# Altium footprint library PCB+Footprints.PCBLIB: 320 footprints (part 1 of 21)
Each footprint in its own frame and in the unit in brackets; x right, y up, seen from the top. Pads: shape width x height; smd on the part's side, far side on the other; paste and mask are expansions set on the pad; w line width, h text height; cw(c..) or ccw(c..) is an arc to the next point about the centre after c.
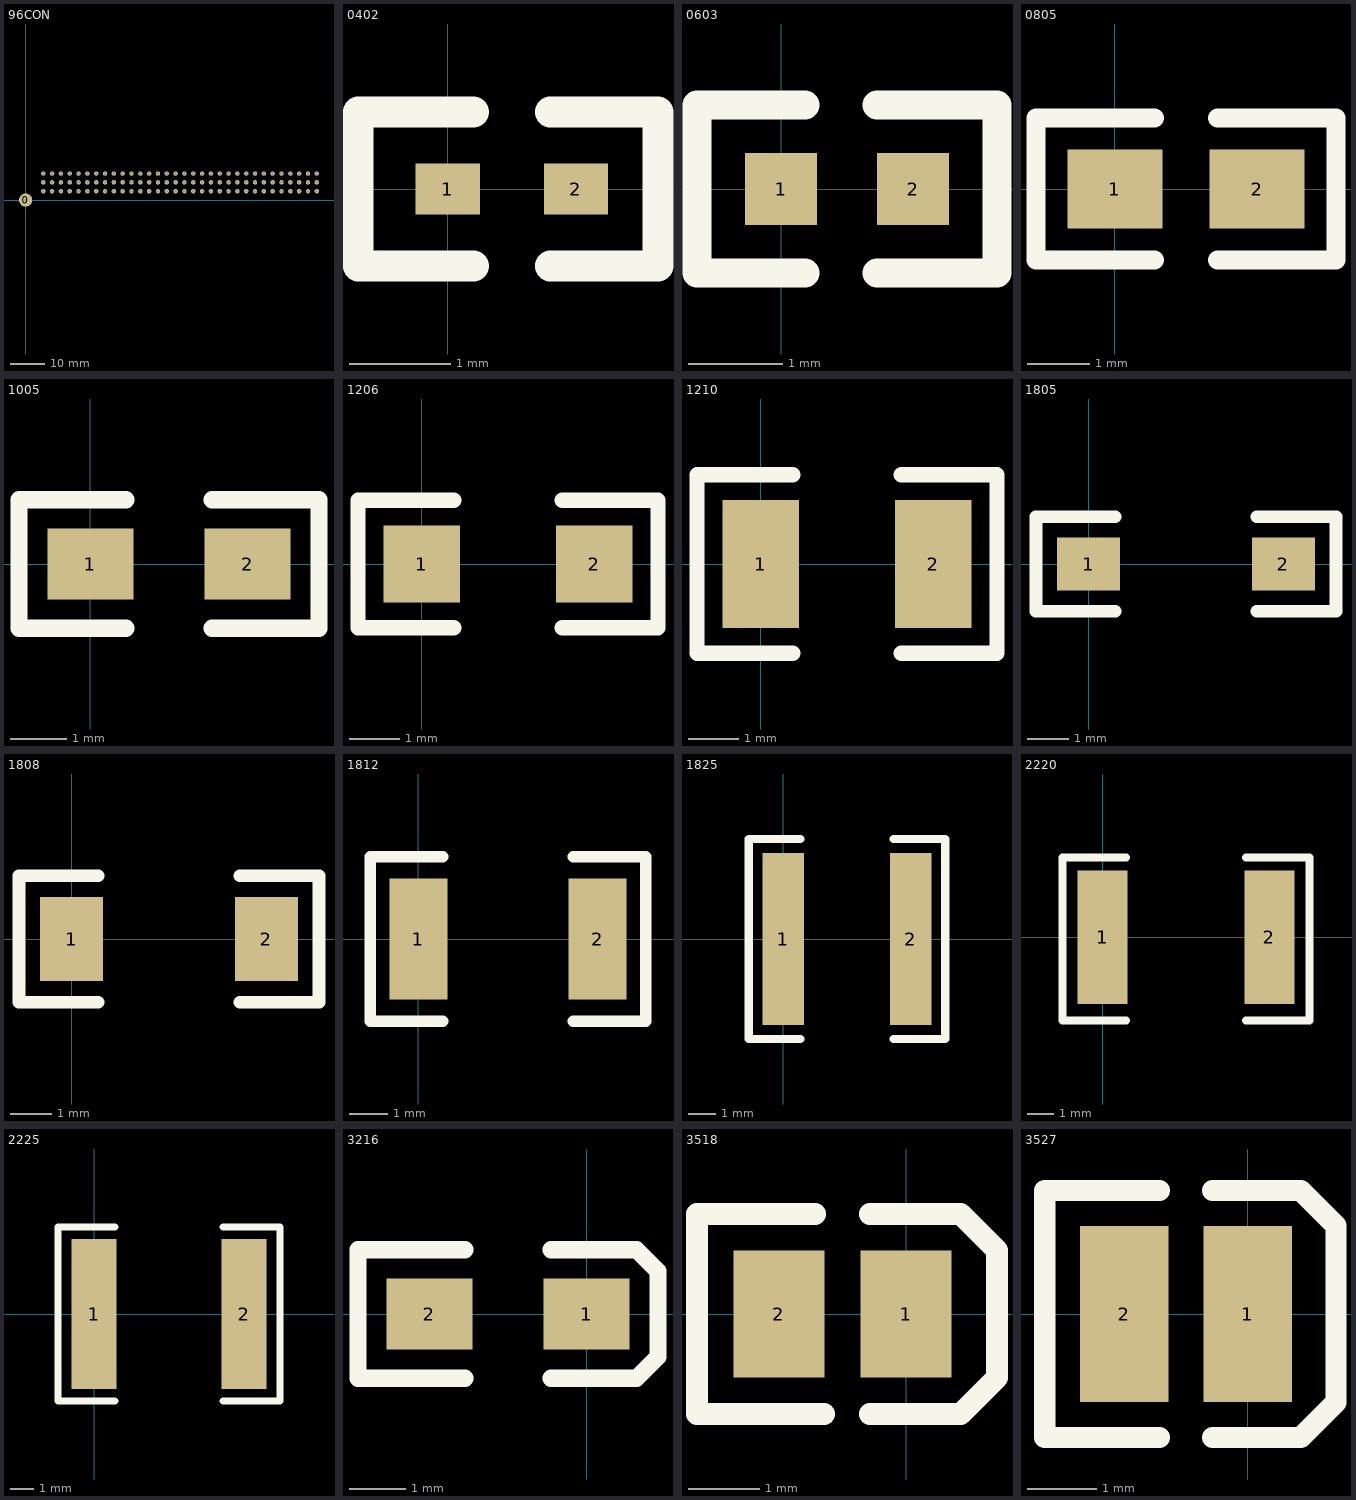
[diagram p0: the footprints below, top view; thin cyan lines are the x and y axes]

## 96CON [mil]
pads (97):
  round 150 hole 30: 0(0,0)
  round 50 hole 30: 1(3300,300) 2(3200,300) 3(3100,300) 4(3000,300) 5(2900,300) 6(2800,300) 7(2700,300) 8(2600,300) 9(2500,300) 10(2400,300) 11(2300,300) 12(2200,300) 13(2100,300) 14(2000,300) 15(1900,300) 16(1800,300) 17(1700,300) 18(1600,300) 19(1500,300) 20(1400,300) 21(1300,300) 22(1200,300) 23(1100,300) 24(1000,300) 25(900,300) 26(800,300) 27(700,300) 28(600,300) 29(500,300) 30(400,300) 31(300,300) 32(200,300) 33(3300,200) 34(3200,200) 35(3100,200) 36(3000,200) 37(2900,200) 38(2800,200) 39(2700,200) 40(2600,200) 41(2500,200) 42(2400,200) 43(2300,200) 44(2200,200) 45(2100,200) 46(2000,200) 47(1900,200) 48(1800,200) 49(1700,200) 50(1600,200) 51(1500,200) 52(1400,200) 53(1300,200) 54(1200,200) 55(1100,200) 56(1000,200) 57(900,200) 58(800,200) 59(700,200) 60(600,200) 61(500,200) 62(400,200) 63(300,200) 64(200,200) 65(3300,100) 66(3200,100) 67(3100,100) 68(3000,100) 69(2900,100) 70(2800,100) 71(2700,100) 72(2600,100) 73(2500,100) 74(2400,100) 75(2300,100) 76(2200,100) 77(2100,100) 78(2000,100) 79(1900,100) 80(1800,100) 81(1700,100) 82(1600,100) 83(1500,100) 84(1400,100) 85(1300,100) 86(1200,100) 87(1100,100) 88(1000,100) 89(900,100) 90(800,100) 91(700,100) 92(600,100) 93(500,100) 94(400,100) 95(300,100) 96(200,100)

## 0402 [mil]
pads (2):
  rect 25x20 smd: 1(0,0) 2(50,0)
TopOverlay:
  lines w12: 10,-30 -35,-30 -35,30 10,30 ; 40,-30 82,-30 82,30 40,30

## 0603 [mil]
pads (2):
  rect 30x30 smd: 1(0,0) 2(55,0)
TopOverlay:
  lines w12: 10,-35 -35,-35 -35,35 10,35 ; 40,-35 90,-35 90,35 40,35

## 0805 [mil]
pads (2):
  rect 60x50 smd: 1(0,0) 2(90,0)
TopOverlay:
  lines w12: 25,-45 -50,-45 -50,45 25,45 ; 65,-45 140,-45 140,45 65,45

## 1005 [mil]
pads (2):
  rect 60x50 smd: 1(0,0) 2(110,0)
TopOverlay:
  lines w12: 25,-45 -50,-45 -50,45 25,45 ; 85,-45 160,-45 160,45 85,45

## 1206 [mil]
pads (2):
  rect 60x60 smd: 1(0,0) 2(135,0)
TopOverlay:
  lines w12: 25,-50 -50,-50 -50,50 25,50 ; 110,-50 185,-50 185,50 110,50

## 1210 [mil]
pads (2):
  rect 60x100 smd: 1(0,0) 2(135,0)
TopOverlay:
  lines w12: 25,-70 -50,-70 -50,70 25,70 ; 110,-70 185,-70 185,70 110,70

## 1805 [mil]
pads (2):
  rect 60x50 smd: 1(0,0) 2(185,0)
TopOverlay:
  lines w12: 25,-45 -50,-45 -50,45 25,45 ; 160,-45 235,-45 235,45 160,45

## 1808 [mil]
pads (2):
  rect 60x80 smd: 1(0,0) 2(185,0)
TopOverlay:
  lines w12: 25,-60 -50,-60 -50,60 25,60 ; 160,-60 235,-60 235,60 160,60

## 1812 [mil]
pads (2):
  rect 60x125 smd: 1(0,0) 2(185,0)
TopOverlay:
  lines w12: 25,-85 -50,-85 -50,85 25,85 ; 160,-85 235,-85 235,85 160,85

## 1825 [mil]
pads (2):
  rect 60x250 smd: 1(0,0) 2(185,0)
TopOverlay:
  lines w12: 25,-145 -50,-145 -50,145 25,145 ; 160,-145 235,-145 235,145 160,145

## 2220 [mil]
pads (2):
  rect 75x200 smd: 1(0,0) 2(250,0)
TopOverlay:
  lines w12: 35,-125 -60,-125 -60,120 35,120 ; 215,-125 310,-125 310,120 215,120

## 2225 [mil]
pads (2):
  rect 75x250 smd: 1(0,0) 2(250,0)
TopOverlay:
  lines w12: 35,-145 -60,-145 -60,145 35,145 ; 215,-145 310,-145 310,145 215,145

## 3216 [mil]
pads (2):
  rect 60x50 smd: 1(0,0) 2(-110,0)
TopOverlay:
  lines w12: -85,-45 -160,-45 -160,45 -85,45 ; -25,-45 35,-45 50,-30 50,30 35,45 -25,45

## 3518 [mil]
pads (2):
  rect 50x70 smd: 1(0,0) 2(-70,0)
TopOverlay:
  lines w12: -50,55 -115,55 -115,-55 -45,-55 ; -20,-55 30,-55 50,-35 50,35 30,55 -20,55

## 3527 [mil]
pads (2):
  rect 50x100 smd: 1(0,0) 2(-70,0)
TopOverlay:
  lines w12: -50,-70 -115,-70 -115,70 -50,70 ; -20,-70 30,-70 50,-50 50,50 30,70 -20,70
